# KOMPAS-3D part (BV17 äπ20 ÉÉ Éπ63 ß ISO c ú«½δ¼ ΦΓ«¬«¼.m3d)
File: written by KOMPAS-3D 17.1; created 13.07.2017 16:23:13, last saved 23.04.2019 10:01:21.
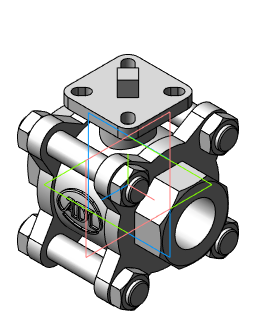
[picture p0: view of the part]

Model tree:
1. Операция без истории:3  (labels: Сталь 20  ГОСТ 1050-88)

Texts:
  DISO1
  DISO2
  BV17 Ду8 1/4" Ру63 с ISO
  BV17 Ду8 СС Ру63 с ISO
  BV17 Ду10 3/8" Ру63 с ISO
  BV17 Ду10 СС Ру63 с ISO
  BV17 Ду15 1/2" Ру63 с ISO
  BV17 Ду15 СС Ру63 с ISO
  BV17 Ду15 ФФ Ру40 с ISO
  BV17 Ду20 3/4" Ру63 с ISO
  BV17 Ду20 СС Ру40 с ISO
  BV17 Ду20 ФФ Ру40 с ISO
  BV17 Ду25 1" Ру63 с ISO
  BV17 Ду25 СС Ру63 с ISO
  BV17 Ду25 ФФ Ру40 с ISO
  BV17 Ду32 1 1/4" Ру63 с ISO
  BV17 Ду32 СС Ру63 с ISO
  BV17 Ду32 ФФ Ру40 с ISO
  BV17 Ду40 1 1/2" Ру63 с ISO
  BV17 Ду40 СС Ру63 с ISO
  BV17 Ду40 ФФ Ру40 с ISO
  BV17 Ду50 2" Ру63 с ISO
  BV17 Ду50 СС Ру63 с ISO
  BV17 Ду50 ФФ Ру40 с ISO
  BV17 Ду65 2 1/2" Ру40 с ISO
  BV17 Ду65 СС Ру40 с ISO
  BV17 Ду65 ФФ Ру40 с ISO
  BV17 Ду80 3" Ру40 с ISO
  BV17 Ду80 СС Ру40 с ISO
  BV17 Ду80 ФФ Ру40 с ISO
  BV17 Ду100 4" Ру40 с ISO
  BV17 Ду100 СС Ру40 с ISO
  BV17 Ду100 ФФ Ру40 с ISO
